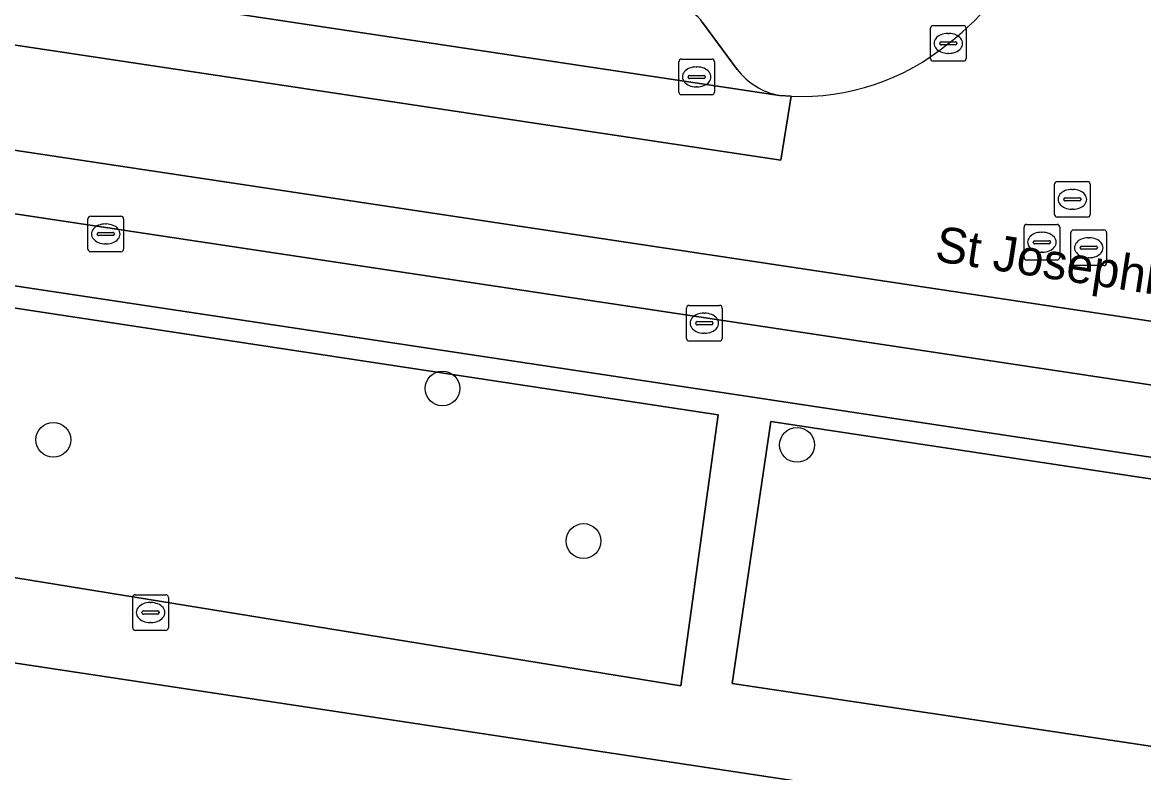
# Model space of a CAD drawing. Extents: x 163008 to 163854, y 382777 to 383982.
# Drawn here: x 163577.85 to 163609.33, y 383192.22 to 383213.27 of the extents above; entities that cross this region are included whole.
import ezdxf

# ---------------------------------------------------------------- set-up
doc = ezdxf.new("R2010")
doc.units = 0
for name, color, linetype in [('IMGEO_Boom', 7, 'Continuous'), ('IMGEO_Brandkraan', 7, 'Continuous'), ('IMGEO_Erf', 7, 'Continuous'), ('IMGEO_Groenvoorziening', 7, 'Continuous'), ('IMGEO_Kolk', 7, 'Continuous'), ('IMGEO_Openbare_ruimte_label', 7, 'Continuous'), ('IMGEO_Parkeervlak_open', 7, 'Continuous'), ('IMGEO_Rijbaan_lokaal_gesloten', 7, 'Continuous'), ('IMGEO_Rijbaan_lokaal_open', 7, 'Continuous'), ('IMGEO_Rioolput', 7, 'Continuous'), ('IMGEO_Voetpad_open', 7, 'Continuous')]:
    doc.layers.add(name, color=color, linetype=linetype)

msp = doc.modelspace()

# ---------------------------------------------------------------- linework, layer by layer
at = {"layer": 'IMGEO_Boom'}
for centre in [(163589.645, 383202.999), (163578.72, 383201.558), (163599.599, 383201.415), (163593.604, 383198.716)]:
    msp.add_circle(centre, 0.489, dxfattribs=at)
at = {"layer": 'IMGEO_Brandkraan'}
for p, q in [((163581.023, 383197.21), (163581.875, 383197.21)), ((163580.948, 383196.284), (163580.948, 383197.136)), ((163581.436, 383196.99), (163581.461, 383196.99)), ((163581.949, 383197.136), (163581.949, 383196.284)), ((163581.207, 383196.704), (163581.207, 383196.716)), ((163581.645, 383196.667), (163581.247, 383196.667)), ((163581.25, 383196.753), (163581.648, 383196.753)), ((163581.691, 383196.716), (163581.691, 383196.704)), ((163581.459, 383196.43), (163581.434, 383196.43)), ((163581.875, 383196.21), (163581.023, 383196.21))]:
    msp.add_line(p, q, dxfattribs=at)
for points in [[(163581.023, 383197.21), (163581.875, 383197.21)], [(163580.948, 383196.284), (163580.948, 383197.136)], [(163581.949, 383197.136), (163581.949, 383196.284)], [(163581.875, 383196.21), (163581.023, 383196.21)]]:
    msp.add_lwpolyline(points, dxfattribs=at)
for centre, radius, start, end in [((163581.025, 383197.134), 0.0765, 91.552, 178.448), ((163581.025, 383197.134), 0.0765, 91.552, 178.448), ((163581.873, 383197.134), 0.0765, 1.552, 88.448), ((163581.873, 383197.134), 0.0765, 1.552, 88.448), ((163581.247, 383196.713), 0.0403, 85.8775, 175.7526), ((163581.244, 383196.703), 0.0366, 178.938, 274.7102), ((163581.648, 383196.71), 0.043, 264.8664, 352.4533), ((163581.652, 383196.715), 0.0386, 1.7309, 96.639), ((163581.025, 383196.286), 0.0765, 181.552, 268.448), ((163581.025, 383196.286), 0.0765, 181.552, 268.448), ((163581.873, 383196.286), 0.0765, 271.552, 358.448), ((163581.873, 383196.286), 0.0765, 271.552, 358.448)]:
    msp.add_arc(centre, radius, start, end, dxfattribs=at)
for centre, major_axis, ratio, start_param, end_param in [((163581.435, 383196.71), (-0.387, 0.002), 0.722429, 4.712389, 7.853982), ((163581.46, 383196.71), (-0.39, 0.002), 0.717154, 1.570796, 4.712389)]:
    msp.add_ellipse(centre, major_axis=major_axis, ratio=ratio, start_param=start_param, end_param=end_param, dxfattribs=at)
at = {"layer": 'IMGEO_Erf'}
msp.add_lwpolyline([(163666.122, 383181.928), (163548.798, 383199.652), (163548.213, 383195.706), (163553.285, 383194.942), (163558.601, 383194.14), (163563.917, 383193.339), (163569.233, 383192.538), (163574.55, 383191.736), (163579.866, 383190.935), (163585.182, 383190.133), (163590.498, 383189.332), (163595.983, 383188.505), (163595.85, 383187.617), (163601.098, 383186.826), (163606.339, 383186.036), (163611.579, 383185.246)], dxfattribs=at)
at = {"layer": 'IMGEO_Groenvoorziening'}
for points in [[(163596.336, 383194.649), (163597.387, 383202.259), (163571.857, 383206.128), (163570.738, 383198.808)], [(163611.269, 383192.7), (163612.484, 383200.013), (163598.861, 383202.068), (163597.776, 383194.721)]]:
    msp.add_lwpolyline(points, close=True, dxfattribs=at)
at = {"layer": 'IMGEO_Kolk'}
for p, q in [((163603.345, 383212.259), (163603.345, 383213.111)), ((163603.42, 383213.185), (163604.272, 383213.185)), ((163603.833, 383212.965), (163603.858, 383212.965)), ((163604.346, 383213.111), (163604.346, 383212.259)), ((163603.604, 383212.679), (163603.604, 383212.691)), ((163604.042, 383212.642), (163603.644, 383212.642)), ((163603.647, 383212.728), (163604.045, 383212.728)), ((163604.088, 383212.691), (163604.088, 383212.679)), ((163603.856, 383212.405), (163603.831, 383212.405)), ((163596.279, 383211.318), (163596.279, 383212.17)), ((163596.354, 383212.244), (163597.206, 383212.244)), ((163596.767, 383212.024), (163596.792, 383212.024)), ((163597.28, 383212.17), (163597.28, 383211.318)), ((163604.272, 383212.185), (163603.42, 383212.185)), ((163596.538, 383211.738), (163596.538, 383211.75)), ((163596.976, 383211.701), (163596.578, 383211.701)), ((163596.581, 383211.787), (163596.979, 383211.787)), ((163597.022, 383211.75), (163597.022, 383211.738)), ((163596.79, 383211.464), (163596.765, 383211.464)), ((163597.206, 383211.244), (163596.354, 383211.244)), ((163579.692, 383206.91), (163579.692, 383207.762)), ((163579.767, 383207.836), (163580.619, 383207.836)), ((163580.18, 383207.616), (163580.205, 383207.616)), ((163580.693, 383207.762), (163580.693, 383206.91)), ((163579.951, 383207.33), (163579.951, 383207.342)), ((163580.389, 383207.293), (163579.991, 383207.293)), ((163579.994, 383207.379), (163580.392, 383207.379)), ((163580.435, 383207.342), (163580.435, 383207.33)), ((163580.203, 383207.056), (163580.178, 383207.056)), ((163580.619, 383206.836), (163579.767, 383206.836)), ((163596.495, 383204.405), (163596.495, 383205.257)), ((163596.57, 383205.331), (163597.422, 383205.331)), ((163596.983, 383205.111), (163597.008, 383205.111)), ((163597.496, 383205.257), (163597.496, 383204.405)), ((163596.754, 383204.825), (163596.754, 383204.837)), ((163597.192, 383204.788), (163596.794, 383204.788)), ((163596.797, 383204.874), (163597.195, 383204.874)), ((163597.238, 383204.837), (163597.238, 383204.825)), ((163597.006, 383204.551), (163596.981, 383204.551)), ((163597.422, 383204.331), (163596.57, 383204.331))]:
    msp.add_line(p, q, dxfattribs=at)
for points in [[(163603.345, 383212.259), (163603.345, 383213.111)], [(163603.42, 383213.185), (163604.272, 383213.185)], [(163604.346, 383213.111), (163604.346, 383212.259)], [(163596.279, 383211.318), (163596.279, 383212.17)], [(163596.354, 383212.244), (163597.206, 383212.244)], [(163597.28, 383212.17), (163597.28, 383211.318)], [(163604.272, 383212.185), (163603.42, 383212.185)], [(163597.206, 383211.244), (163596.354, 383211.244)], [(163579.692, 383206.91), (163579.692, 383207.762)], [(163579.767, 383207.836), (163580.619, 383207.836)], [(163580.693, 383207.762), (163580.693, 383206.91)], [(163580.619, 383206.836), (163579.767, 383206.836)], [(163596.495, 383204.405), (163596.495, 383205.257)], [(163596.57, 383205.331), (163597.422, 383205.331)], [(163597.496, 383205.257), (163597.496, 383204.405)], [(163597.422, 383204.331), (163596.57, 383204.331)]]:
    msp.add_lwpolyline(points, dxfattribs=at)
for centre, radius, start, end in [((163603.422, 383213.109), 0.0765, 91.552, 178.448), ((163603.422, 383213.109), 0.0765, 91.552, 178.448), ((163604.27, 383213.109), 0.0765, 1.552, 88.448), ((163604.27, 383213.109), 0.0765, 1.552, 88.448), ((163603.644, 383212.688), 0.0403, 85.8775, 175.7526), ((163603.641, 383212.678), 0.0366, 178.938, 274.7102), ((163604.045, 383212.685), 0.043, 264.8664, 352.4533), ((163604.049, 383212.69), 0.0386, 1.7309, 96.639), ((163596.356, 383212.168), 0.0765, 91.552, 178.448), ((163596.356, 383212.168), 0.0765, 91.552, 178.448), ((163597.204, 383212.168), 0.0765, 1.552, 88.448), ((163597.204, 383212.168), 0.0765, 1.552, 88.448), ((163603.422, 383212.261), 0.0765, 181.552, 268.448), ((163603.422, 383212.261), 0.0765, 181.552, 268.448), ((163604.27, 383212.261), 0.0765, 271.552, 358.448), ((163604.27, 383212.261), 0.0765, 271.552, 358.448), ((163596.578, 383211.747), 0.0403, 85.8775, 175.7526), ((163596.575, 383211.737), 0.0366, 178.938, 274.7102), ((163596.979, 383211.744), 0.043, 264.8664, 352.4533), ((163596.983, 383211.749), 0.0386, 1.7309, 96.639), ((163596.356, 383211.32), 0.0765, 181.552, 268.448), ((163596.356, 383211.32), 0.0765, 181.552, 268.448), ((163597.204, 383211.32), 0.0765, 271.552, 358.448), ((163597.204, 383211.32), 0.0765, 271.552, 358.448), ((163579.769, 383207.76), 0.0765, 91.552, 178.448), ((163579.769, 383207.76), 0.0765, 91.552, 178.448), ((163580.617, 383207.76), 0.0765, 1.552, 88.448), ((163580.617, 383207.76), 0.0765, 1.552, 88.448), ((163579.991, 383207.339), 0.0403, 85.8775, 175.7526), ((163579.988, 383207.329), 0.0366, 178.938, 274.7102), ((163580.392, 383207.336), 0.043, 264.8664, 352.4533), ((163580.396, 383207.341), 0.0386, 1.7309, 96.639), ((163579.769, 383206.912), 0.0765, 181.552, 268.448), ((163579.769, 383206.912), 0.0765, 181.552, 268.448), ((163580.617, 383206.912), 0.0765, 271.552, 358.448), ((163580.617, 383206.912), 0.0765, 271.552, 358.448), ((163596.572, 383205.255), 0.0765, 91.552, 178.448), ((163596.572, 383205.255), 0.0765, 91.552, 178.448), ((163597.42, 383205.255), 0.0765, 1.552, 88.448), ((163597.42, 383205.255), 0.0765, 1.552, 88.448), ((163596.794, 383204.834), 0.0403, 85.8775, 175.7526), ((163596.791, 383204.824), 0.0366, 178.938, 274.7102), ((163597.195, 383204.831), 0.043, 264.8664, 352.4533), ((163597.199, 383204.836), 0.0386, 1.7309, 96.639), ((163596.572, 383204.407), 0.0765, 181.552, 268.448), ((163596.572, 383204.407), 0.0765, 181.552, 268.448), ((163597.42, 383204.407), 0.0765, 271.552, 358.448), ((163597.42, 383204.407), 0.0765, 271.552, 358.448)]:
    msp.add_arc(centre, radius, start, end, dxfattribs=at)
for centre, major_axis, ratio, start_param, end_param in [((163603.832, 383212.685), (-0.387, 0.002), 0.722429, 4.712389, 7.853982), ((163603.857, 383212.685), (-0.39, 0.002), 0.717154, 1.570796, 4.712389), ((163596.766, 383211.744), (-0.387, 0.002), 0.722429, 4.712389, 7.853982), ((163596.791, 383211.744), (-0.39, 0.002), 0.717154, 1.570796, 4.712389), ((163580.179, 383207.336), (-0.387, 0.002), 0.722429, 4.712389, 7.853982), ((163580.204, 383207.336), (-0.39, 0.002), 0.717154, 1.570796, 4.712389), ((163596.982, 383204.831), (-0.387, 0.002), 0.722429, 4.712389, 7.853982), ((163597.007, 383204.831), (-0.39, 0.002), 0.717154, 1.570796, 4.712389)]:
    msp.add_ellipse(centre, major_axis=major_axis, ratio=ratio, start_param=start_param, end_param=end_param, dxfattribs=at)
at = {"layer": 'IMGEO_Parkeervlak_open'}
for points in [[(163551.582, 383218.367), (163599.104, 383211.221)], [(163597.914, 383211.952), (163596.948, 383213.273)], [(163662.995, 383195.049), (163661.651, 383195.247), (163550.601, 383211.967)], [(163553.174, 383209.562), (163659.72, 383193.503)]]:
    msp.add_lwpolyline(points, dxfattribs=at)
for centre, radius, start, end in [((163596.173, 383212.752), 0.933, 33.9028, 81.701), ((163599.506, 383213.21), 2.029, 218.3128, 258.5636)]:
    msp.add_arc(centre, radius, start, end, dxfattribs=at)
at = {"layer": 'IMGEO_Rijbaan_lokaal_gesloten'}
for points in [[(163551.317, 383216.605), (163599.147, 383209.408), (163599.431, 383211.199), (163599.104, 383211.221), (163551.582, 383218.367)], [(163661.902, 383197.008), (163550.863, 383213.714), (163550.601, 383211.967), (163661.651, 383195.247)]]:
    msp.add_lwpolyline(points, close=True, dxfattribs=at)
at = {"layer": 'IMGEO_Rijbaan_lokaal_open'}
msp.add_lwpolyline([(163599.431, 383211.199), (163599.147, 383209.408), (163551.317, 383216.605), (163550.863, 383213.714), (163661.902, 383197.008), (163662.359, 383199.897), (163614.572, 383207.077), (163614.81, 383208.857)], dxfattribs=at)
for centre, radius, start, end in [((163599.715, 383218.176), 6.872, 306.9552, 350.9455), ((163599.708, 383217.677), 6.484, 267.5512, 309.6532)]:
    msp.add_arc(centre, radius, start, end, dxfattribs=at)
at = {"layer": 'IMGEO_Rioolput'}
for p, q in [((163606.828, 383207.882), (163606.828, 383208.734)), ((163606.903, 383208.808), (163607.755, 383208.808)), ((163607.316, 383208.588), (163607.341, 383208.588)), ((163607.829, 383208.734), (163607.829, 383207.882)), ((163607.087, 383208.302), (163607.087, 383208.314)), ((163607.525, 383208.265), (163607.127, 383208.265)), ((163607.13, 383208.351), (163607.528, 383208.351)), ((163607.571, 383208.314), (163607.571, 383208.302)), ((163607.339, 383208.028), (163607.314, 383208.028)), ((163606.047, 383207.604), (163606.899, 383207.604)), ((163607.755, 383207.808), (163606.903, 383207.808)), ((163605.972, 383206.678), (163605.972, 383207.53)), ((163606.46, 383207.384), (163606.485, 383207.384)), ((163606.973, 383207.53), (163606.973, 383206.678)), ((163607.289, 383206.523), (163607.289, 383207.375)), ((163607.364, 383207.449), (163608.216, 383207.449)), ((163608.29, 383207.375), (163608.29, 383206.523)), ((163606.231, 383207.098), (163606.231, 383207.11)), ((163606.669, 383207.061), (163606.271, 383207.061)), ((163606.274, 383207.147), (163606.672, 383207.147)), ((163606.715, 383207.11), (163606.715, 383207.098)), ((163607.591, 383206.992), (163607.989, 383206.992)), ((163607.777, 383207.229), (163607.802, 383207.229)), ((163606.483, 383206.824), (163606.458, 383206.824)), ((163607.548, 383206.943), (163607.548, 383206.955)), ((163607.986, 383206.906), (163607.588, 383206.906)), ((163607.8, 383206.669), (163607.775, 383206.669)), ((163608.032, 383206.955), (163608.032, 383206.943)), ((163606.899, 383206.604), (163606.047, 383206.604)), ((163608.216, 383206.449), (163607.364, 383206.449))]:
    msp.add_line(p, q, dxfattribs=at)
for points in [[(163606.828, 383207.882), (163606.828, 383208.734)], [(163606.903, 383208.808), (163607.755, 383208.808)], [(163607.829, 383208.734), (163607.829, 383207.882)], [(163606.047, 383207.604), (163606.899, 383207.604)], [(163607.755, 383207.808), (163606.903, 383207.808)], [(163605.972, 383206.678), (163605.972, 383207.53)], [(163606.973, 383207.53), (163606.973, 383206.678)], [(163607.289, 383206.523), (163607.289, 383207.375)], [(163607.364, 383207.449), (163608.216, 383207.449)], [(163608.29, 383207.375), (163608.29, 383206.523)], [(163606.899, 383206.604), (163606.047, 383206.604)], [(163608.216, 383206.449), (163607.364, 383206.449)]]:
    msp.add_lwpolyline(points, dxfattribs=at)
for centre, radius, start, end in [((163606.905, 383208.732), 0.0765, 91.552, 178.448), ((163606.905, 383208.732), 0.0765, 91.552, 178.448), ((163607.753, 383208.732), 0.0765, 1.552, 88.448), ((163607.753, 383208.732), 0.0765, 1.552, 88.448), ((163607.127, 383208.311), 0.0403, 85.8775, 175.7526), ((163607.124, 383208.301), 0.0366, 178.938, 274.7102), ((163607.528, 383208.308), 0.043, 264.8664, 352.4533), ((163607.532, 383208.313), 0.0386, 1.7309, 96.639), ((163606.049, 383207.528), 0.0765, 91.552, 178.448), ((163606.049, 383207.528), 0.0765, 91.552, 178.448), ((163606.905, 383207.884), 0.0765, 181.552, 268.448), ((163606.905, 383207.884), 0.0765, 181.552, 268.448), ((163606.897, 383207.528), 0.0765, 1.552, 88.448), ((163606.897, 383207.528), 0.0765, 1.552, 88.448), ((163607.753, 383207.884), 0.0765, 271.552, 358.448), ((163607.753, 383207.884), 0.0765, 271.552, 358.448), ((163607.366, 383207.373), 0.0765, 91.552, 178.448), ((163607.366, 383207.373), 0.0765, 91.552, 178.448), ((163608.214, 383207.373), 0.0765, 1.552, 88.448), ((163608.214, 383207.373), 0.0765, 1.552, 88.448), ((163606.271, 383207.107), 0.0403, 85.8775, 175.7526), ((163606.268, 383207.097), 0.0366, 178.938, 274.7102), ((163606.672, 383207.104), 0.043, 264.8664, 352.4533), ((163606.676, 383207.109), 0.0386, 1.7309, 96.639), ((163607.588, 383206.952), 0.0403, 85.8775, 175.7526), ((163607.993, 383206.954), 0.0386, 1.7309, 96.639), ((163606.049, 383206.68), 0.0765, 181.552, 268.448), ((163606.049, 383206.68), 0.0765, 181.552, 268.448), ((163606.897, 383206.68), 0.0765, 271.552, 358.448), ((163606.897, 383206.68), 0.0765, 271.552, 358.448), ((163607.585, 383206.942), 0.0366, 178.938, 274.7102), ((163607.989, 383206.949), 0.043, 264.8664, 352.4533), ((163607.366, 383206.525), 0.0765, 181.552, 268.448), ((163607.366, 383206.525), 0.0765, 181.552, 268.448), ((163608.214, 383206.525), 0.0765, 271.552, 358.448), ((163608.214, 383206.525), 0.0765, 271.552, 358.448)]:
    msp.add_arc(centre, radius, start, end, dxfattribs=at)
for centre, major_axis, ratio, start_param, end_param in [((163607.315, 383208.308), (-0.387, 0.002), 0.722429, 4.712389, 7.853982), ((163607.34, 383208.308), (-0.39, 0.002), 0.717154, 1.570796, 4.712389), ((163606.459, 383207.104), (-0.387, 0.002), 0.722429, 4.712389, 7.853982), ((163606.484, 383207.104), (-0.39, 0.002), 0.717154, 1.570796, 4.712389), ((163607.776, 383206.949), (-0.387, 0.002), 0.722429, 4.712389, 7.853982), ((163607.801, 383206.949), (-0.39, 0.002), 0.717154, 1.570796, 4.712389)]:
    msp.add_ellipse(centre, major_axis=major_axis, ratio=ratio, start_param=start_param, end_param=end_param, dxfattribs=at)
at = {"layer": 'IMGEO_Voetpad_open'}
for points in [[(163596.948, 383213.273), (163597.914, 383211.952)], [(163599.104, 383211.221), (163599.431, 383211.199)], [(163659.72, 383193.503), (163553.174, 383209.562)], [(163546.356, 383200.021), (163548.798, 383199.652), (163666.122, 383181.928), (163667.379, 383181.747), (163668.321, 383188.294)]]:
    msp.add_lwpolyline(points, dxfattribs=at)
for points in [[(163596.336, 383194.649), (163570.738, 383198.808), (163571.857, 383206.128), (163597.387, 383202.259)], [(163611.269, 383192.7), (163597.776, 383194.721), (163598.861, 383202.068), (163612.484, 383200.013)]]:
    msp.add_lwpolyline(points, close=True, dxfattribs=at)
for centre, radius, start, end in [((163599.715, 383218.176), 6.872, 306.9552, 350.9455), ((163596.173, 383212.752), 0.933, 33.9028, 81.701), ((163599.708, 383217.677), 6.484, 267.5512, 309.6532), ((163599.506, 383213.21), 2.029, 218.3128, 258.5636)]:
    msp.add_arc(centre, radius, start, end, dxfattribs=at)

# ---------------------------------------------------------------- texts
at = {"layer": 'IMGEO_Openbare_ruimte_label'}
msp.add_text('St Josephlaan', height=1, rotation=351.3191, dxfattribs=at).set_placement((163603.439, 383206.58))

doc.saveas('drawing.dxf')
